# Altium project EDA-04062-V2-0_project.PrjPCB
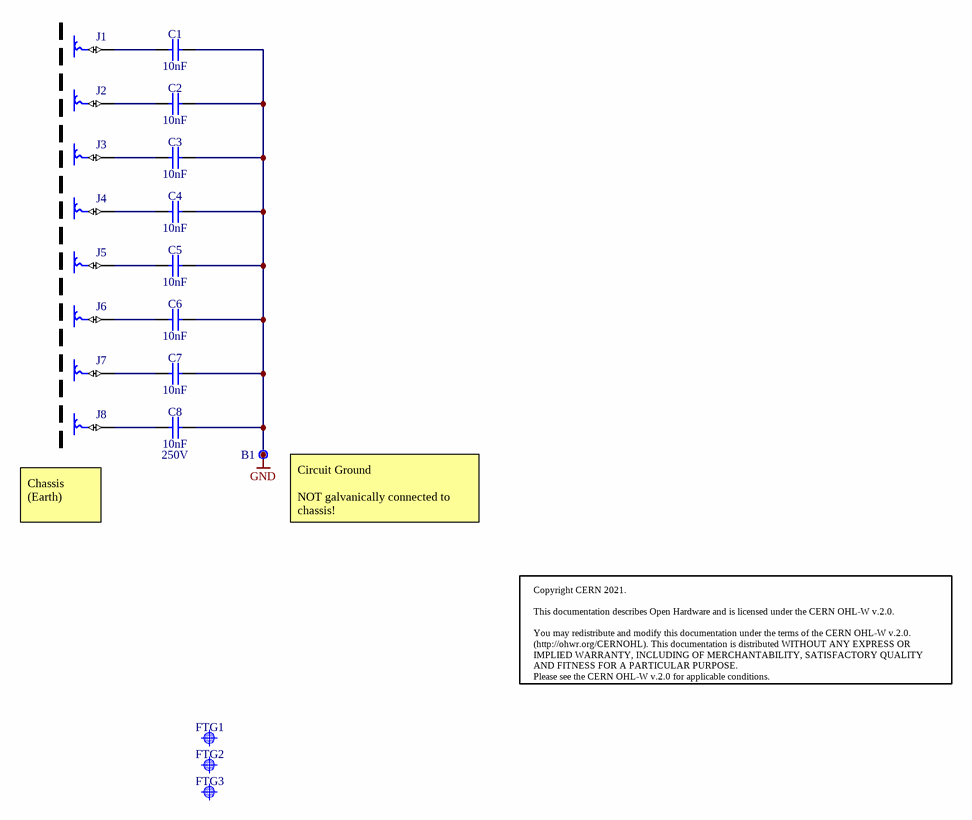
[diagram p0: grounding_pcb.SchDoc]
1 sheet, 20 parts. Net scope: global (net labels, ports and power ports of the same name join across sheets).
Board file: EDA-04062-V2-0_pcb.pcbdoc

## Sheet grounding_pcb.SchDoc: HPM7177
size 297 x 209 mm; CheckedBy: JMW; CompanyName: CERN; DrawnBy: N. Beev; Organization: CERN; Address1: European Organization for Nuclear Research; Address2: CH-1211 Genève 23 - Switzerland; Revision: -; SheetNumber: 1; SheetTotal: 1; EDA_Number: EDA-04062-V2-0; Projet: HPM7177; ModifiedBy: B. Civel; CreateDate: 04-04-2019; CheckedDate: 21-05-2019; Title2: Grounding Board; DivGrp: TE/EPC; Designer: N. Beev

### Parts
B1  Plated Hole  [MTG950H1300V8P]  (value not drawn)  (no BOM)
C1  10nF  [CAPC1608X87N]
C2  10nF  [CAPC1608X87N]
C3  10nF  [CAPC1608X87N]
C4  10nF  [CAPC1608X87N]
C5  10nF  [CAPC1608X87N]
C6  10nF  [CAPC1608X87N]
C7  10nF  [CAPC1608X87N]
C8  10nF  Voltage: 250V  [CAPC1608X87N]
FTG1  Use only in PCB  [FIDUCIAL_TOP_C100-200]  (value not drawn)
FTG2  Use only in PCB  [FIDUCIAL_TOP_C100-200]  (value not drawn)
FTG3  Use only in PCB  [FIDUCIAL_TOP_C100-200]  (value not drawn)
J1  (no value)  [LAIRD_BMI-C-004]
J2  (no value)  [LAIRD_BMI-C-004]
J3  (no value)  [LAIRD_BMI-C-004]
J4  (no value)  [LAIRD_BMI-C-004]
J5  (no value)  [LAIRD_BMI-C-004]
J6  (no value)  [LAIRD_BMI-C-004]
J7  (no value)  [LAIRD_BMI-C-004]
J8  (no value)  [LAIRD_BMI-C-004]

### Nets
GND: B1.1 C1.2 C2.2 C3.2 C4.2 C5.2 C6.2 C7.2 C8.2
NetC1_1: C1.1 J1.1
NetC2_1: C2.1 J2.1
NetC3_1: C3.1 J3.1
NetC4_1: C4.1 J4.1
NetC5_1: C5.1 J5.1
NetC6_1: C6.1 J6.1
NetC7_1: C7.1 J7.1
NetC8_1: C8.1 J8.1

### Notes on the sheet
- (near J8) Chassis
  (Earth)
- (near B1) Circuit Ground
  NOT galvanically connected to chassis!
- Copyright CERN 2021.
  This documentation describes Open Hardware and is licensed under the CERN OHL-W v.2.0.
  You may redistribute and modify this documentation under the terms of the CERN OHL-W v.2.0. (http://ohwr.org/CERNOHL). This documentation is distributed WITHOUT ANY EXPRESS OR IMPLIED WARRANTY, INCLUDING OF MERCHANTABILITY, SATISFACTORY QUALITY AND FITNESS FOR A PARTICULAR PURPOSE.
  Please see the CERN OHL-W v.2.0 for applicable conditions.

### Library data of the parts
B1 = PLATED_HOLE9.5_PAD13.0_8VIA: Single Terminal Socket; Part Description: Plated Through Hole: Hole Dia.=9.5mm Pad Dia.=13.0mm + 8 Via Dia.=0.5mm; Mounted: No
C1-C7 = CC0603_10NF_250V_10%_X7R_KEMET_C0603C103KARACAUTO: Non-polarised capacitor; Part Description: SMD Multilayer Chip Ceramic Capacitor (Automotive Grade); Manufacturer: KEMET; Voltage: 250V; TC: X7R; Tolerance: ±10%
C8 = CC0603_10NF_250V_10%_X7R_KEMET_C0603C103KARACAUTO: Non-polarised capacitor; Part Description: SMD Multilayer Chip Ceramic Capacitor (Automotive Grade); Manufacturer: KEMET; TC: X7R; Tolerance: ±10%
FTG1-FTG3 = FIDUCIAL_TARGET_C100-200: Fiducial Target; Part Description: Round Fiducial Target, Top Layer, 1.0mm, Top Solder 2.0mm, Keepout =2.0mm; Mounted: No
J1-J8 = LAIRD_BMI-C-004: Spring Contact; Part Description: Surface Mount Standard Precision EMI Gasket Grounding Contact; Manufacturer: LAIRD; PressFit: No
